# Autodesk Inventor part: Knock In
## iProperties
Shininess: 64.0
Length Units: 11269
Angle Units: 11279
Time Units: 11290
Mass Units: 11283
Length Display Precision: 3
Angle Display Precision: 2
Compacted: True
Part Number: Knock In
Document SubType Name: Sheet Metal
Created: 2003-04
Designer: Andy
Density: 0.0
Volumn: 0.0
Area: 0.0
PropertySet Name: Model Information
Control State: 0
Master: False
Checked Out: False
Author: Andy Marshall
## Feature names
1. Extrusion1
2. Extrusion2
3. Plate1
